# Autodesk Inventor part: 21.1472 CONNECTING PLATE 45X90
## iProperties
Created: 2007-01
Part Number: 21.1472 CONNECTING PLATE 45X90
Document SubType Name: Modeling
Designer: Andy Moles
Material: Aluminum-6061
Mass: 154.918 g
Surface Area: 125.881 cm^2
Volume: 57.1653 cm^3
Density: 2.71 g/cm^3
Author: Andy Moles
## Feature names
1. Extrusion1
2. Hole1
3. Hole2
4. Fillet1
